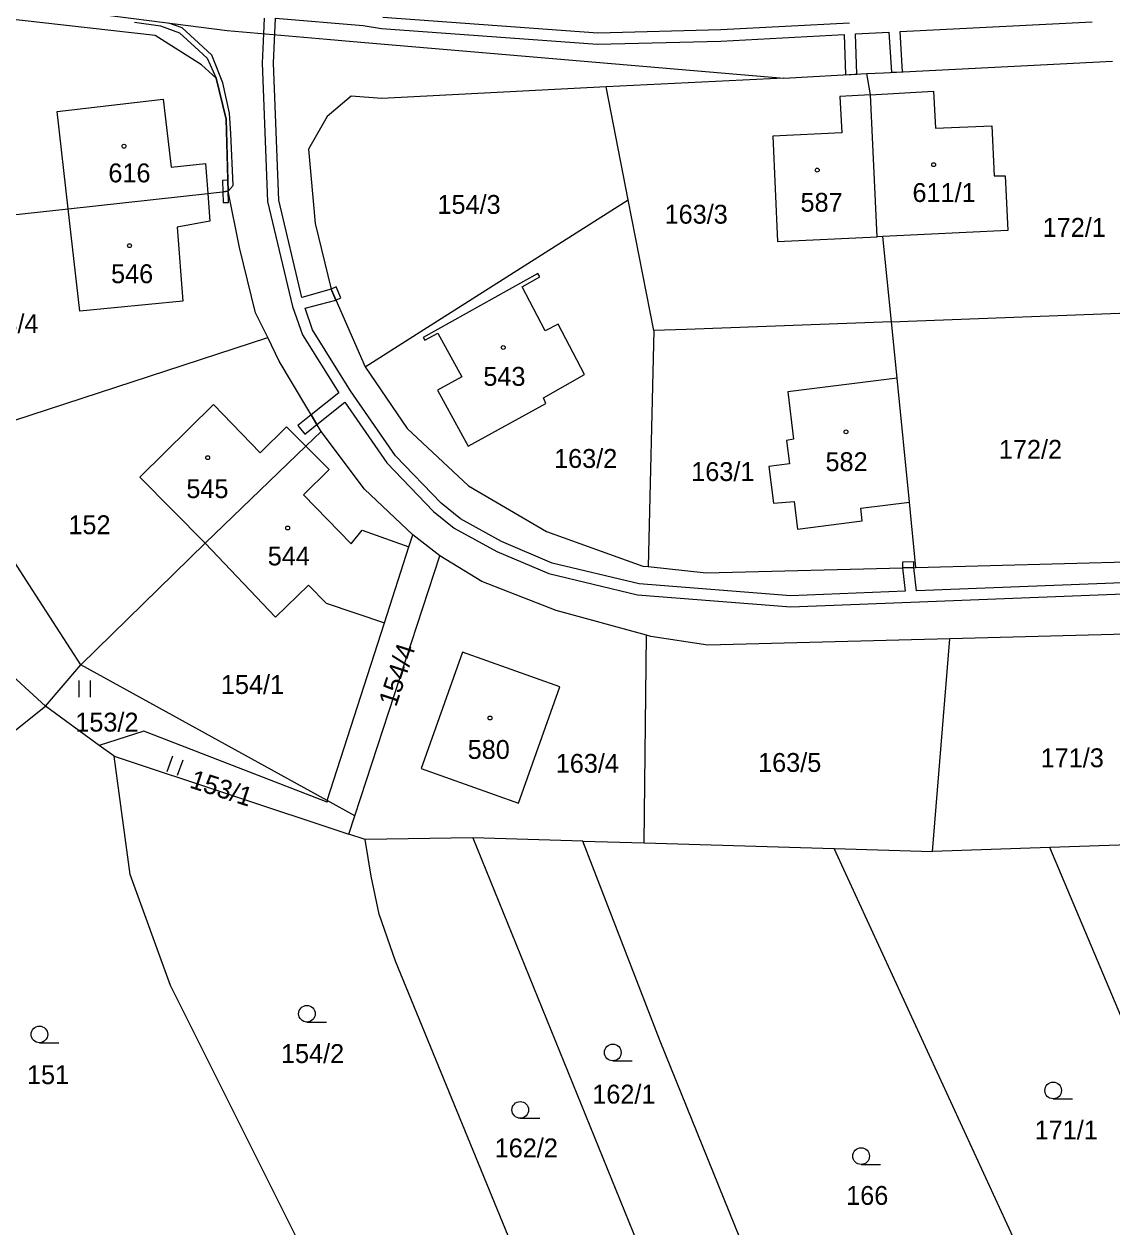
# Model space of a CAD drawing. Extents: x -776734 to -748832, y -1118122 to -976986.
# Drawn here: x -753275.1 to -753177.2, y -1115546.1 to -1115437.8 of the extents above; entities that cross this region are included whole.
import ezdxf

# ---------------------------------------------------------------- set-up
doc = ezdxf.new("R2010")
doc.units = 0
for name, color, linetype in [('KM_Hranice parcel', 7, 'Continuous'), ('KM_Parcelní čísla', 7, 'Continuous'), ('KM_Vnitřní kresba', 7, 'Continuous'), ('KM_Věcná břemena k části', 7, 'Continuous'), ('KM_Značky budov', 7, 'Continuous'), ('KM_Značky kultur', 7, 'Continuous')]:
    doc.layers.add(name, color=color, linetype=linetype)

msp = doc.modelspace()

# ---------------------------------------------------------------- linework, layer by layer
at = {"layer": 'KM_Hranice parcel'}
for p, q in [((-753206.71, -1115442.68), (-753199.25, -1115442.28)), ((-753198.92, -1115444.19), (-753199.25, -1115442.28)), ((-753206.71, -1115442.68), (-753222.72, -1115443.48)), ((-753220.72, -1115453.66), (-753222.72, -1115443.48)), ((-753198.3, -1115456.97), (-753198.92, -1115444.19)), ((-753271.14, -1115454.45), (-753258.58, -1115453.08)), ((-753258.58, -1115453.08), (-753256.74, -1115452.88)), ((-753218.41, -1115465.42), (-753220.72, -1115453.66)), ((-753285.17, -1115455.98), (-753271.14, -1115454.45)), ((-753197.79, -1115456.95), (-753198.3, -1115456.97)), ((-753197.02, -1115464.62), (-753197.79, -1115456.95)), ((-753196.51, -1115469.71), (-753197.02, -1115464.62)), ((-753282.78, -1115475.72), (-753253.18, -1115466.05)), ((-753218.41, -1115465.42), (-753218.92, -1115486.67)), ((-753195.4, -1115480.87), (-753196.51, -1115469.71)), ((-753248.38, -1115474.5), (-753249.74, -1115475.82)), ((-753249.74, -1115475.82), (-753258.81, -1115484.57)), ((-753194.82, -1115486.74), (-753195.4, -1115480.87)), ((-753270, -1115495.52), (-753258.81, -1115484.57)), ((-753237.68, -1115485.7), (-753240.12, -1115483.8)), ((-753245.35, -1115509.1), (-753237.68, -1115485.7)), ((-753194.82, -1115486.74), (-753172.67, -1115486.15)), ((-753247.83, -1115507.73), (-753242.67, -1115491.73)), ((-753219.3, -1115511.55), (-753219.09, -1115492.84)), ((-753193.33, -1115512.32), (-753191.76, -1115493.16)), ((-753171.88, -1115492.64), (-753191.76, -1115493.16)), ((-753273.18, -1115499.22), (-753270, -1115495.52)), ((-753247.83, -1115507.73), (-753270, -1115495.52)), ((-753300.05, -1115520.55), (-753273.18, -1115499.22)), ((-753268.35, -1115502.76), (-753273.18, -1115499.22)), ((-753267.01, -1115503.74), (-753268.35, -1115502.76)), ((-753267.01, -1115503.74), (-753245.89, -1115510.76)), ((-753245.35, -1115509.1), (-753247.83, -1115507.73)), ((-753245.89, -1115510.76), (-753245.35, -1115509.1)), ((-753244.42, -1115511.25), (-753245.89, -1115510.76)), ((-753234.72, -1115511.09), (-753244.42, -1115511.25)), ((-753234.72, -1115511.09), (-753216.41, -1115556.11)), ((-753224.81, -1115511.39), (-753234.72, -1115511.09)), ((-753224.81, -1115511.39), (-753219.3, -1115511.55)), ((-753219.3, -1115511.55), (-753202.17, -1115512.06)), ((-753164.78, -1115511.33), (-753182.77, -1115511.96)), ((-753202.17, -1115512.06), (-753193.33, -1115512.32)), ((-753177.75, -1115565.03), (-753202.17, -1115512.06)), ((-753182.77, -1115511.96), (-753193.33, -1115512.32)), ((-753173.34, -1115534.33), (-753182.77, -1115511.96))]:
    msp.add_line(p, q, dxfattribs=at)
for points in [[(-753287.78, -1115434.4), (-753256.83, -1115438.41), (-753247.86, -1115439.17), (-753245.5, -1115439.38), (-753206.71, -1115442.68)], [(-753256.74, -1115452.88), (-753256.92, -1115446.38), (-753257.82, -1115442.69), (-753259.16, -1115441.5), (-753263.33, -1115438.86), (-753287.57, -1115436.12)], [(-753199.25, -1115442.28), (-753197.75, -1115442.2), (-753177.13, -1115441.15)], [(-753222.72, -1115443.48), (-753242.9, -1115444.51), (-753245.66, -1115444.32), (-753247.82, -1115446.13), (-753249.5, -1115449.08), (-753248.9, -1115455.78), (-753247.48, -1115461.68), (-753244.42, -1115468.67)], [(-753271.14, -1115454.45), (-753272.13, -1115445.68), (-753262.61, -1115444.57), (-753261.87, -1115450.69), (-753258.79, -1115450.37), (-753258.58, -1115453.08)], [(-753198.92, -1115444.19), (-753201.68, -1115444.33), (-753201.5, -1115447.62), (-753207.71, -1115447.92), (-753207.27, -1115457.41), (-753198.3, -1115456.97)], [(-753198.92, -1115444.19), (-753193.25, -1115443.87), (-753193.05, -1115447.2), (-753187.98, -1115446.97), (-753187.76, -1115451.48), (-753186.79, -1115451.47), (-753186.55, -1115456.41), (-753197.79, -1115456.95)], [(-753258.58, -1115453.08), (-753258.39, -1115455.58), (-753261.35, -1115456.1), (-753260.84, -1115462.77), (-753270.09, -1115463.67), (-753271.14, -1115454.45)], [(-753253.18, -1115466.05), (-753254.28, -1115463.83), (-753255.72, -1115457.93), (-753256.74, -1115452.88)], [(-753244.42, -1115468.67), (-753239.46, -1115465.53), (-753220.72, -1115453.66)], [(-753228.68, -1115460.57), (-753228.85, -1115460.27), (-753239.18, -1115466.03), (-753239.04, -1115466.29), (-753237.87, -1115465.65), (-753235.71, -1115469.59), (-753237.9, -1115470.79), (-753235.14, -1115475.82), (-753228.14, -1115471.98), (-753228.36, -1115471.46), (-753224.65, -1115469.38), (-753227.03, -1115464.83), (-753228.2, -1115465.44), (-753230.28, -1115461.48), (-753228.68, -1115460.57)], [(-753197.02, -1115464.62), (-753195.52, -1115464.56), (-753174.89, -1115463.79)], [(-753197.02, -1115464.62), (-753215.51, -1115465.31), (-753218.41, -1115465.42)], [(-753248.38, -1115474.5), (-753252.14, -1115468.16), (-753253.18, -1115466.05)], [(-753244.42, -1115468.67), (-753240.64, -1115474.22), (-753235.12, -1115479.38), (-753228.08, -1115483.5), (-753219.42, -1115486.62), (-753218.92, -1115486.67)], [(-753196.51, -1115469.71), (-753206.35, -1115470.92), (-753205.84, -1115475.2), (-753206.46, -1115475.3), (-753206.2, -1115477.41), (-753208.05, -1115477.65), (-753207.65, -1115480.95), (-753205.79, -1115480.79), (-753205.49, -1115483.29), (-753199.67, -1115482.54), (-753199.77, -1115481.4), (-753195.4, -1115480.87)], [(-753249.74, -1115475.82), (-753251.49, -1115474.07), (-753253.85, -1115476.42), (-753258.08, -1115472.08), (-753264.69, -1115478.6), (-753258.81, -1115484.57)], [(-753240.12, -1115483.8), (-753244.48, -1115479.7), (-753248.38, -1115474.5)], [(-753270, -1115495.52), (-753274.66, -1115488.31), (-753282.78, -1115475.72)], [(-753295.47, -1115480.93), (-753277.23, -1115495.51), (-753273.18, -1115499.22)], [(-753258.81, -1115484.57), (-753252.47, -1115491.21), (-753249.51, -1115488.35), (-753247.92, -1115489.97), (-753242.67, -1115491.73)], [(-753242.67, -1115491.73), (-753240.47, -1115484.89), (-753240.12, -1115483.8)], [(-753219.09, -1115492.84), (-753227.22, -1115490.62), (-753233.92, -1115488), (-753237.68, -1115485.7)], [(-753218.92, -1115486.67), (-753213.72, -1115487.24), (-753194.82, -1115486.74)], [(-753191.76, -1115493.16), (-753213.55, -1115493.74), (-753218.7, -1115492.95), (-753219.09, -1115492.84)], [(-753239.36, -1115504.83), (-753230.59, -1115507.95), (-753226.87, -1115497.5), (-753235.64, -1115494.37), (-753239.36, -1115504.83)], [(-753247.83, -1115507.73), (-753247.83, -1115507.87), (-753264.34, -1115501.47), (-753268.35, -1115502.76)], [(-753249.7, -1115548.87), (-753261.94, -1115524.38), (-753265.56, -1115514.39), (-753267.01, -1115503.74)], [(-753231.06, -1115548.08), (-753241.68, -1115522.2), (-753243.16, -1115517.97), (-753243.86, -1115514.53), (-753244.42, -1115511.25)], [(-753209.2, -1115550.73), (-753217.86, -1115529.4), (-753224.81, -1115511.39)]]:
    msp.add_lwpolyline(points, dxfattribs=at)
at = {"layer": 'KM_Vnitřní kresba'}
for p, q in [((-753249.74, -1115475.82), (-753247.64, -1115477.93)), ((-753247.64, -1115477.93), (-753249.97, -1115480.19)), ((-753249.97, -1115480.19), (-753245.66, -1115484.63)), ((-753245.66, -1115484.63), (-753244.69, -1115483.39)), ((-753244.69, -1115483.39), (-753240.47, -1115484.89))]:
    msp.add_line(p, q, dxfattribs=at)
at = {"layer": 'KM_Věcná břemena k části'}
for points in [[(-753265.17, -1115437.66), (-753262.83, -1115437.99), (-753261.14, -1115438.6), (-753259.75, -1115439.87), (-753258.63, -1115440.9), (-753257.82, -1115442.69), (-753256.92, -1115446.38), (-753256.77, -1115451.88), (-753256.74, -1115452.88), (-753256.29, -1115452.35), (-753256.52, -1115447.68), (-753256.63, -1115445.83), (-753257.24, -1115443.1), (-753258.21, -1115440.62), (-753259.41, -1115439.51), (-753260.88, -1115438.16), (-753262.09, -1115437.73)], [(-753253.5, -1115437.29), (-753253.56, -1115438.69), (-753253.67, -1115441.34), (-753253.19, -1115453.81), (-753250.94, -1115463.24), (-753250.06, -1115465.79), (-753246.79, -1115471.03), (-753249.27, -1115473), (-753248.76, -1115473.87), (-753246.24, -1115471.86), (-753242.45, -1115477.33), (-753238.26, -1115481.7), (-753236.4, -1115483.2), (-753232.56, -1115485.32), (-753227.88, -1115487.3), (-753219.89, -1115489.22), (-753206.07, -1115490.3), (-753195.28, -1115489.87), (-753172.28, -1115488.98), (-753128.12, -1115487.85), (-753127.94, -1115491.48), (-753126.95, -1115491.45), (-753127.13, -1115487.82), (-753118.66, -1115487.72)], [(-753172.34, -1115487.98), (-753194.76, -1115488.85), (-753195.01, -1115486.75), (-753196.02, -1115486.77), (-753195.8, -1115488.89), (-753206.08, -1115489.3), (-753219.73, -1115488.23), (-753227.57, -1115486.35), (-753232.13, -1115484.42), (-753235.84, -1115482.37), (-753237.58, -1115480.96), (-753241.67, -1115476.69), (-753245.72, -1115470.85), (-753249.15, -1115465.36), (-753249.82, -1115463.41), (-753247.05, -1115462.67), (-753247.48, -1115461.68), (-753250.1, -1115462.45), (-753252.19, -1115453.68), (-753252.67, -1115441.35), (-753252.49, -1115437.29), (-753244.58, -1115437.95), (-753242.93, -1115438.23), (-753223.5, -1115439.63), (-753212.4, -1115439.35), (-753201.27, -1115438.76), (-753201.15, -1115442.38), (-753200.15, -1115442.33), (-753200.27, -1115438.7), (-753197.25, -1115438.55), (-753197.02, -1115442.16), (-753196.02, -1115442.11), (-753196.25, -1115438.5), (-753178.96, -1115437.63)], [(-753200.8, -1115437.73), (-753212.4, -1115438.35), (-753223.47, -1115438.63), (-753242.83, -1115437.23)]]:
    msp.add_lwpolyline(points, dxfattribs=at)
for points in [[(-753257.24, -1115452.93), (-753256.74, -1115452.88), (-753256.77, -1115451.88), (-753257.27, -1115451.89)], [(-753256.71, -1115453.88), (-753256.74, -1115452.88), (-753257.24, -1115452.93), (-753257.21, -1115453.89)], [(-753247.48, -1115461.68), (-753247.05, -1115462.67), (-753246.59, -1115462.47), (-753247.02, -1115461.48)], [(-753248.76, -1115473.87), (-753249.27, -1115473), (-753250.47, -1115473.96), (-753249.85, -1115474.74)], [(-753196.02, -1115486.77), (-753195.01, -1115486.75), (-753195.02, -1115486.25), (-753196.03, -1115486.27)]]:
    msp.add_lwpolyline(points, close=True, dxfattribs=at)
at = {"layer": 'KM_Značky budov'}
for centre in [(-753266.1268, -1115448.8192), (-753203.7068, -1115450.9692), (-753193.2268, -1115450.4792), (-753265.6268, -1115457.7692), (-753231.9768, -1115466.9392), (-753201.1168, -1115474.5292), (-753258.5868, -1115476.8592), (-753251.3868, -1115483.1892), (-753233.1668, -1115500.2992)]:
    msp.add_circle(centre, 0.175, dxfattribs=at)
at = {"layer": 'KM_Značky kultur'}
for p, q in [((-753270.151, -1115498.41), (-753270.151, -1115496.91)), ((-753269.15, -1115498.41), (-753269.15, -1115496.91)), ((-753262.24, -1115505.115), (-753261.727, -1115503.706)), ((-753261.299, -1115505.458), (-753260.786, -1115504.048)), ((-753249.653, -1115527.67), (-753247.903, -1115527.67)), ((-753273.743, -1115529.53), (-753271.993, -1115529.53)), ((-753222.113, -1115531.16), (-753220.363, -1115531.16)), ((-753182.463, -1115534.58), (-753180.713, -1115534.58)), ((-753230.443, -1115536.33), (-753228.693, -1115536.33)), ((-753199.753, -1115540.49), (-753198.003, -1115540.49))]:
    msp.add_line(p, q, dxfattribs=at)
for centre in [(-753249.6529, -1115526.9198), (-753273.7429, -1115528.7798), (-753222.1129, -1115530.4098), (-753182.4629, -1115533.8298), (-753230.4429, -1115535.5798), (-753199.7529, -1115539.7398)]:
    msp.add_circle(centre, 0.75, dxfattribs=at)

# ---------------------------------------------------------------- texts
at = {"layer": 'KM_Parcelní čísla'}
for s, p in [('616', (-753267.53, -1115452.07)), ('611/1', (-753195.13, -1115453.84)), ('154/3', (-753237.9, -1115454.91)), ('587', (-753205.21, -1115454.72)), ('163/3', (-753217.45, -1115455.79)), ('172/1', (-753183.41, -1115456.98)), ('546', (-753267.29, -1115461.15)), ('143/4', (-753279.51, -1115465.64)), ('543', (-753233.77, -1115470.39)), ('163/2', (-753227.4, -1115477.78)), ('172/2', (-753187.35, -1115476.96)), ('582', (-753202.96, -1115478.07)), ('163/1', (-753215.05, -1115478.96)), ('545', (-753260.51, -1115480.5)), ('152', (-753271.13, -1115483.75)), ('544', (-753253.18, -1115486.56)), ('154/1', (-753257.4, -1115498.13)), ('153/2', (-753270.51, -1115501.52)), ('580', (-753235.18, -1115503.98)), ('171/3', (-753183.59, -1115504.73)), ('163/4', (-753227.25, -1115505.23)), ('163/5', (-753209.03, -1115505.15)), ('154/2', (-753251.99, -1115531.36)), ('151', (-753274.86, -1115533.26)), ('162/1', (-753223.96, -1115535.01)), ('171/1', (-753184.13, -1115538.24)), ('162/2', (-753232.75, -1115539.85)), ('166', (-753201.1, -1115544.13))]:
    msp.add_text(s, height=1.7, dxfattribs=at).set_placement(p)
for s, rotation, p in [('154/4', 72, (-753241.621, -1115499.362)), ('153/1', 342, (-753260.312, -1115506.538))]:
    msp.add_text(s, height=1.7, rotation=rotation, dxfattribs=at).set_placement(p)

doc.saveas('drawing.dxf')
